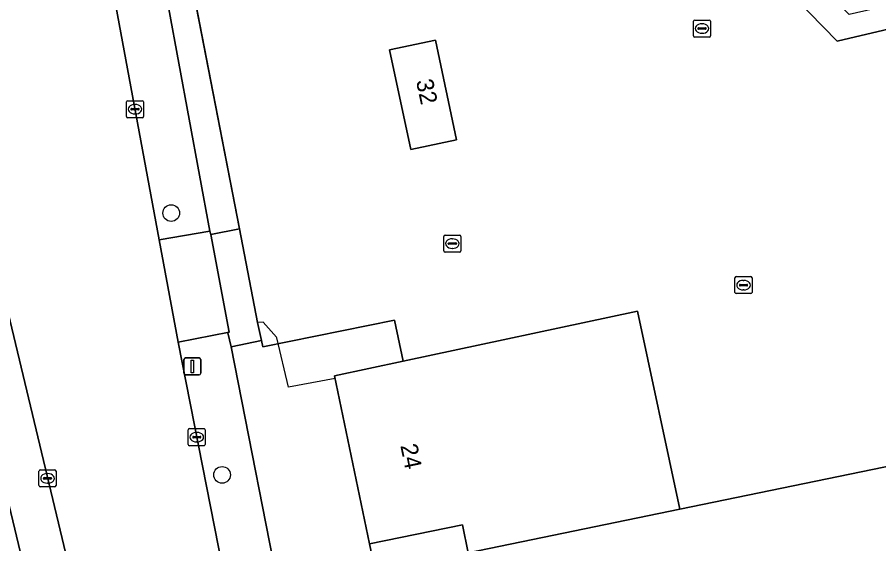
# Model space of a CAD drawing. Extents: x 162989 to 165008, y 383432 to 384338.
# Drawn here: x 164275.7 to 164326.4, y 384168.5 to 384199.5 of the extents above; entities that cross this region are included whole.
import ezdxf

# ---------------------------------------------------------------- set-up
doc = ezdxf.new("R2010")
doc.units = 0
for name, color, linetype in [('IMGEO_Boom', 7, 'Continuous'), ('IMGEO_Erf', 7, 'Continuous'), ('IMGEO_Groenvoorziening', 7, 'Continuous'), ('IMGEO_Hek', 7, 'Continuous'), ('IMGEO_Kolk', 7, 'Continuous'), ('IMGEO_Lichtmast', 7, 'Continuous'), ('IMGEO_Pand', 7, 'Continuous'), ('IMGEO_Pand_nummerreeks', 7, 'Continuous'), ('IMGEO_Rijbaan_lokaal_open', 7, 'Continuous'), ('IMGEO_Rioolput', 7, 'Continuous'), ('IMGEO_Voetpad_halfverhard', 7, 'Continuous'), ('IMGEO_Voetpad_open', 7, 'Continuous')]:
    doc.layers.add(name, color=color, linetype=linetype)

msp = doc.modelspace()

# ---------------------------------------------------------------- linework, layer by layer
at = {"layer": 'IMGEO_Boom'}
for centre in [(164284.791, 384187.967), (164287.78, 384172.593)]:
    msp.add_circle(centre, 0.489, dxfattribs=at)
at = {"layer": 'IMGEO_Erf'}
for points in [[(164352.012, 384189.272), (164351.666, 384190.951), (164349.03, 384203.686), (164345.88, 384203.022), (164345.767, 384203.225), (164323.902, 384198.058), (164310.007, 384212.304), (164284.923, 384207.017), (164288.795, 384187.032), (164289.861, 384181.531), (164290.088, 384180.487), (164290.168, 384180.119), (164297.901, 384181.683), (164298.416, 384179.266), (164312.176, 384182.207), (164314.663, 384170.574), (164349.272, 384177.712), (164354.784, 384150.783), (164357.983, 384135.415), (164362.896, 384136.438), (164362.509, 384138.318)], [(164301.552, 384192.268), (164298.858, 384191.689), (164297.623, 384197.555), (164300.321, 384198.122)]]:
    msp.add_lwpolyline(points, close=True, dxfattribs=at)
at = {"layer": 'IMGEO_Groenvoorziening'}
msp.add_lwpolyline([(164310.007, 384212.304), (164323.902, 384198.058), (164345.767, 384203.225), (164345.88, 384203.022), (164349.03, 384203.686), (164348.736, 384205.107), (164324.619, 384199.625), (164311.134, 384213.146)], close=True, dxfattribs=at)
msp.add_lwpolyline([(164279.829, 384151.74), (164269.173, 384196.228)], dxfattribs=at)
at = {"layer": 'IMGEO_Hek'}
for points in [[(164288.795, 384187.032), (164284.873, 384207.276)], [(164290.967, 384180.671), (164290.186, 384181.569), (164289.861, 384181.531), (164288.795, 384187.032)], [(164294.423, 384178.244), (164291.682, 384177.752), (164290.991, 384180.644), (164290.967, 384180.671)]]:
    msp.add_lwpolyline(points, dxfattribs=at)
at = {"layer": 'IMGEO_Kolk'}
for p, q in [((164282.24, 384194.562), (164283.092, 384194.562)), ((164282.165, 384193.636), (164282.165, 384194.488)), ((164282.424, 384194.056), (164282.424, 384194.068)), ((164282.862, 384194.019), (164282.464, 384194.019)), ((164282.467, 384194.105), (164282.865, 384194.105)), ((164282.653, 384194.342), (164282.678, 384194.342)), ((164282.908, 384194.068), (164282.908, 384194.056)), ((164283.166, 384194.488), (164283.166, 384193.636)), ((164283.092, 384193.562), (164282.24, 384193.562)), ((164282.676, 384193.782), (164282.651, 384193.782)), ((164300.805, 384185.746), (164300.805, 384186.598)), ((164300.88, 384186.672), (164301.732, 384186.672)), ((164301.293, 384186.452), (164301.318, 384186.452)), ((164301.806, 384186.598), (164301.806, 384185.746)), ((164301.064, 384186.166), (164301.064, 384186.178)), ((164301.502, 384186.129), (164301.104, 384186.129)), ((164301.107, 384186.215), (164301.505, 384186.215)), ((164301.548, 384186.178), (164301.548, 384186.166)), ((164301.732, 384185.672), (164300.88, 384185.672)), ((164301.316, 384185.892), (164301.291, 384185.892)), ((164317.906, 384183.308), (164317.906, 384184.16)), ((164317.981, 384184.234), (164318.833, 384184.234)), ((164318.394, 384184.014), (164318.419, 384184.014)), ((164318.907, 384184.16), (164318.907, 384183.308)), ((164318.165, 384183.728), (164318.165, 384183.74)), ((164318.603, 384183.691), (164318.205, 384183.691)), ((164318.208, 384183.777), (164318.606, 384183.777)), ((164318.417, 384183.454), (164318.392, 384183.454)), ((164318.649, 384183.74), (164318.649, 384183.728)), ((164318.833, 384183.234), (164317.981, 384183.234)), ((164285.869, 384175.308), (164286.721, 384175.308)), ((164285.794, 384174.382), (164285.794, 384175.234)), ((164286.053, 384174.802), (164286.053, 384174.814)), ((164286.096, 384174.851), (164286.494, 384174.851)), ((164286.282, 384175.088), (164286.307, 384175.088)), ((164286.537, 384174.814), (164286.537, 384174.802)), ((164286.795, 384175.234), (164286.795, 384174.382)), ((164286.721, 384174.308), (164285.869, 384174.308)), ((164286.491, 384174.765), (164286.093, 384174.765)), ((164286.305, 384174.528), (164286.28, 384174.528)), ((164277.026, 384171.961), (164277.026, 384172.813)), ((164277.101, 384172.887), (164277.953, 384172.887)), ((164278.027, 384172.813), (164278.027, 384171.961)), ((164277.285, 384172.381), (164277.285, 384172.393)), ((164277.723, 384172.344), (164277.325, 384172.344)), ((164277.328, 384172.43), (164277.726, 384172.43)), ((164277.514, 384172.667), (164277.539, 384172.667)), ((164277.769, 384172.393), (164277.769, 384172.381)), ((164277.953, 384171.887), (164277.101, 384171.887)), ((164277.537, 384172.107), (164277.512, 384172.107))]:
    msp.add_line(p, q, dxfattribs=at)
for points in [[(164282.24, 384194.562), (164283.092, 384194.562)], [(164282.165, 384193.636), (164282.165, 384194.488)], [(164283.166, 384194.488), (164283.166, 384193.636)], [(164283.092, 384193.562), (164282.24, 384193.562)], [(164300.805, 384185.746), (164300.805, 384186.598)], [(164300.88, 384186.672), (164301.732, 384186.672)], [(164301.806, 384186.598), (164301.806, 384185.746)], [(164301.732, 384185.672), (164300.88, 384185.672)], [(164317.906, 384183.308), (164317.906, 384184.16)], [(164317.981, 384184.234), (164318.833, 384184.234)], [(164318.907, 384184.16), (164318.907, 384183.308)], [(164318.833, 384183.234), (164317.981, 384183.234)], [(164285.869, 384175.308), (164286.721, 384175.308)], [(164285.794, 384174.382), (164285.794, 384175.234)], [(164286.795, 384175.234), (164286.795, 384174.382)], [(164286.721, 384174.308), (164285.869, 384174.308)], [(164277.026, 384171.961), (164277.026, 384172.813)], [(164277.101, 384172.887), (164277.953, 384172.887)], [(164278.027, 384172.813), (164278.027, 384171.961)], [(164277.953, 384171.887), (164277.101, 384171.887)]]:
    msp.add_lwpolyline(points, dxfattribs=at)
for centre, radius, start, end in [((164282.242, 384194.486), 0.0765, 91.552, 178.448), ((164282.242, 384194.486), 0.0765, 91.552, 178.448), ((164283.09, 384194.486), 0.0765, 1.552, 88.448), ((164283.09, 384194.486), 0.0765, 1.552, 88.448), ((164282.464, 384194.065), 0.0403, 85.8775, 175.7526), ((164282.461, 384194.055), 0.0366, 178.938, 274.7102), ((164282.865, 384194.062), 0.043, 264.8664, 352.4533), ((164282.869, 384194.067), 0.0386, 1.7309, 96.639), ((164282.242, 384193.638), 0.0765, 181.552, 268.448), ((164282.242, 384193.638), 0.0765, 181.552, 268.448), ((164283.09, 384193.638), 0.0765, 271.552, 358.448), ((164283.09, 384193.638), 0.0765, 271.552, 358.448), ((164300.882, 384186.596), 0.0765, 91.552, 178.448), ((164300.882, 384186.596), 0.0765, 91.552, 178.448), ((164301.73, 384186.596), 0.0765, 1.552, 88.448), ((164301.73, 384186.596), 0.0765, 1.552, 88.448), ((164301.104, 384186.175), 0.0403, 85.8775, 175.7526), ((164301.101, 384186.165), 0.0366, 178.938, 274.7102), ((164301.505, 384186.172), 0.043, 264.8664, 352.4533), ((164301.509, 384186.177), 0.0386, 1.7309, 96.639), ((164300.882, 384185.748), 0.0765, 181.552, 268.448), ((164300.882, 384185.748), 0.0765, 181.552, 268.448), ((164301.73, 384185.748), 0.0765, 271.552, 358.448), ((164301.73, 384185.748), 0.0765, 271.552, 358.448), ((164317.983, 384184.158), 0.0765, 91.552, 178.448), ((164317.983, 384184.158), 0.0765, 91.552, 178.448), ((164318.831, 384184.158), 0.0765, 1.552, 88.448), ((164318.831, 384184.158), 0.0765, 1.552, 88.448), ((164318.205, 384183.737), 0.0403, 85.8775, 175.7526), ((164318.202, 384183.727), 0.0366, 178.938, 274.7102), ((164318.606, 384183.734), 0.043, 264.8664, 352.4533), ((164318.61, 384183.739), 0.0386, 1.7309, 96.639), ((164317.983, 384183.31), 0.0765, 181.552, 268.448), ((164317.983, 384183.31), 0.0765, 181.552, 268.448), ((164318.831, 384183.31), 0.0765, 271.552, 358.448), ((164318.831, 384183.31), 0.0765, 271.552, 358.448), ((164285.871, 384175.232), 0.0765, 91.552, 178.448), ((164285.871, 384175.232), 0.0765, 91.552, 178.448), ((164286.719, 384175.232), 0.0765, 1.552, 88.448), ((164286.719, 384175.232), 0.0765, 1.552, 88.448), ((164286.093, 384174.811), 0.0403, 85.8775, 175.7526), ((164286.09, 384174.801), 0.0366, 178.938, 274.7102), ((164286.494, 384174.808), 0.043, 264.8664, 352.4533), ((164286.498, 384174.813), 0.0386, 1.7309, 96.639), ((164285.871, 384174.384), 0.0765, 181.552, 268.448), ((164285.871, 384174.384), 0.0765, 181.552, 268.448), ((164286.719, 384174.384), 0.0765, 271.552, 358.448), ((164286.719, 384174.384), 0.0765, 271.552, 358.448), ((164277.103, 384172.811), 0.0765, 91.552, 178.448), ((164277.103, 384172.811), 0.0765, 91.552, 178.448), ((164277.951, 384172.811), 0.0765, 1.552, 88.448), ((164277.951, 384172.811), 0.0765, 1.552, 88.448), ((164277.325, 384172.39), 0.0403, 85.8775, 175.7526), ((164277.322, 384172.38), 0.0366, 178.938, 274.7102), ((164277.726, 384172.387), 0.043, 264.8664, 352.4533), ((164277.73, 384172.392), 0.0386, 1.7309, 96.639), ((164277.103, 384171.963), 0.0765, 181.552, 268.448), ((164277.103, 384171.963), 0.0765, 181.552, 268.448), ((164277.951, 384171.963), 0.0765, 271.552, 358.448), ((164277.951, 384171.963), 0.0765, 271.552, 358.448)]:
    msp.add_arc(centre, radius, start, end, dxfattribs=at)
for centre, major_axis, ratio, start_param, end_param in [((164282.652, 384194.062), (-0.387, 0.002), 0.722429, 4.712389, 7.853982), ((164282.677, 384194.062), (-0.39, 0.002), 0.717154, 1.570796, 4.712389), ((164301.292, 384186.172), (-0.387, 0.002), 0.722429, 4.712389, 7.853982), ((164301.317, 384186.172), (-0.39, 0.002), 0.717154, 1.570796, 4.712389), ((164318.393, 384183.734), (-0.387, 0.002), 0.722429, 4.712389, 7.853982), ((164318.418, 384183.734), (-0.39, 0.002), 0.717154, 1.570796, 4.712389), ((164286.281, 384174.808), (-0.387, 0.002), 0.722429, 4.712389, 7.853982), ((164286.306, 384174.808), (-0.39, 0.002), 0.717154, 1.570796, 4.712389), ((164277.513, 384172.387), (-0.387, 0.002), 0.722429, 4.712389, 7.853982), ((164277.538, 384172.387), (-0.39, 0.002), 0.717154, 1.570796, 4.712389)]:
    msp.add_ellipse(centre, major_axis=major_axis, ratio=ratio, start_param=start_param, end_param=end_param, dxfattribs=at)
at = {"layer": 'IMGEO_Lichtmast'}
for p, q in [((164285.537, 384178.562), (164285.537, 384179.362)), ((164285.537, 384179.362), (164285.537, 384178.562)), ((164285.637, 384179.462), (164286.427, 384179.462)), ((164286.427, 384179.462), (164285.637, 384179.462)), ((164286.527, 384179.362), (164286.527, 384178.562)), ((164286.527, 384178.562), (164286.527, 384179.362)), ((164286.427, 384178.462), (164285.637, 384178.462)), ((164285.637, 384178.462), (164286.427, 384178.462))]:
    msp.add_line(p, q, dxfattribs=at)
msp.add_lwpolyline([(164285.957, 384179.337), (164286.107, 384179.337), (164286.107, 384178.587), (164285.957, 384178.587), (164285.957, 384179.337)], dxfattribs=at)
for centre, start, end in [((164285.637, 384179.362), 90, 180), ((164285.637, 384179.362), 90, 180), ((164286.427, 384179.362), 0, 90), ((164286.427, 384179.362), 360, 90), ((164285.637, 384178.562), 180, 270), ((164285.637, 384178.562), 180, 270), ((164286.427, 384178.562), 270, 0), ((164286.427, 384178.562), 270, 0)]:
    msp.add_arc(centre, 0.1, start, end, dxfattribs=at)
at = {"layer": 'IMGEO_Pand'}
for points in [[(164298.858, 384191.689), (164301.552, 384192.268), (164300.321, 384198.122), (164297.623, 384197.555)], [(164312.176, 384182.207), (164298.416, 384179.266), (164294.384, 384178.408), (164296.446, 384168.542), (164301.893, 384169.665), (164302.234, 384168.01), (164314.663, 384170.574)], [(164354.784, 384150.783), (164349.272, 384177.712), (164314.663, 384170.574), (164302.234, 384168.01), (164301.893, 384169.665), (164296.446, 384168.542), (164305.282, 384126.16), (164311.315, 384127.446), (164311.652, 384125.77), (164339.521, 384131.57), (164357.983, 384135.415)]]:
    msp.add_lwpolyline(points, close=True, dxfattribs=at)
at = {"layer": 'IMGEO_Rijbaan_lokaal_open'}
for points in [[(164285.193, 384180.381), (164284.089, 384186.389), (164278.538, 384216.318), (164277.123, 384223.939), (164264.967, 384221.376), (164271.917, 384195.775), (164282.629, 384151.118)], [(164282.769, 384148.733), (164287.477, 384131.405), (164289.232, 384131.808), (164290.539, 384126.149), (164294.921, 384127.125), (164293.661, 384132.762), (164295.367, 384133.159), (164293.981, 384139.327), (164292.295, 384146.556), (164291.539, 384149.798), (164290.373, 384154.797), (164289.565, 384158.641), (164289.321, 384159.803), (164288.3, 384164.665), (164285.193, 384180.381)]]:
    msp.add_lwpolyline(points, dxfattribs=at)
at = {"layer": 'IMGEO_Rioolput'}
for p, q in [((164315.469, 384198.372), (164315.469, 384199.224)), ((164315.544, 384199.298), (164316.396, 384199.298)), ((164315.957, 384199.078), (164315.982, 384199.078)), ((164316.47, 384199.224), (164316.47, 384198.372)), ((164315.728, 384198.792), (164315.728, 384198.804)), ((164316.166, 384198.755), (164315.768, 384198.755)), ((164315.771, 384198.841), (164316.169, 384198.841)), ((164316.212, 384198.804), (164316.212, 384198.792)), ((164316.396, 384198.298), (164315.544, 384198.298)), ((164315.98, 384198.518), (164315.955, 384198.518))]:
    msp.add_line(p, q, dxfattribs=at)
for points in [[(164315.469, 384198.372), (164315.469, 384199.224)], [(164315.544, 384199.298), (164316.396, 384199.298)], [(164316.47, 384199.224), (164316.47, 384198.372)], [(164316.396, 384198.298), (164315.544, 384198.298)]]:
    msp.add_lwpolyline(points, dxfattribs=at)
for centre, radius, start, end in [((164315.546, 384199.222), 0.0765, 91.552, 178.448), ((164315.546, 384199.222), 0.0765, 91.552, 178.448), ((164316.394, 384199.222), 0.0765, 1.552, 88.448), ((164316.394, 384199.222), 0.0765, 1.552, 88.448), ((164315.768, 384198.801), 0.0403, 85.8775, 175.7526), ((164315.765, 384198.791), 0.0366, 178.938, 274.7102), ((164316.169, 384198.798), 0.043, 264.8664, 352.4533), ((164316.173, 384198.803), 0.0386, 1.7309, 96.639), ((164315.546, 384198.374), 0.0765, 181.552, 268.448), ((164315.546, 384198.374), 0.0765, 181.552, 268.448), ((164316.394, 384198.374), 0.0765, 271.552, 358.448), ((164316.394, 384198.374), 0.0765, 271.552, 358.448)]:
    msp.add_arc(centre, radius, start, end, dxfattribs=at)
for centre, major_axis, ratio, start_param, end_param in [((164315.956, 384198.798), (-0.387, 0.002), 0.722429, 4.712389, 7.853982), ((164315.981, 384198.798), (-0.39, 0.002), 0.717154, 1.570796, 4.712389)]:
    msp.add_ellipse(centre, major_axis=major_axis, ratio=ratio, start_param=start_param, end_param=end_param, dxfattribs=at)
at = {"layer": 'IMGEO_Voetpad_halfverhard'}
for points in [[(164284.923, 384207.017), (164283.401, 384206.709), (164283.411, 384206.656), (164287.067, 384186.9), (164287.119, 384186.708), (164288.795, 384187.032)], [(164296.446, 384168.542), (164294.384, 384178.408), (164298.416, 384179.266), (164297.901, 384181.683), (164290.168, 384180.119), (164290.088, 384180.487), (164288.313, 384180.115), (164291.397, 384164.464), (164293.215, 384156.373), (164296.763, 384140.464), (164300.887, 384123.541), (164301.901, 384123.755), (164305.62, 384124.539), (164305.282, 384126.16)]]:
    msp.add_lwpolyline(points, close=True, dxfattribs=at)
at = {"layer": 'IMGEO_Voetpad_open'}
for points in [[(164283.411, 384206.656), (164283.401, 384206.709), (164282.785, 384210.037), (164282.496, 384211.599), (164281.369, 384217.691), (164282.371, 384220.633), (164282.125, 384221.916), (164282.071, 384222.197), (164281.475, 384222.094), (164280.909, 384224.737), (164280.836, 384224.722), (164279.3, 384224.398), (164280.036, 384220.835), (164278.538, 384216.318), (164284.089, 384186.389), (164287.067, 384186.9)], [(164288.795, 384187.032), (164287.119, 384186.708), (164288.201, 384180.968), (164288.119, 384180.939), (164288.313, 384180.115), (164290.088, 384180.487), (164289.861, 384181.531)], [(164288.201, 384180.968), (164287.119, 384186.708), (164287.067, 384186.9), (164284.089, 384186.389), (164285.193, 384180.381)]]:
    msp.add_lwpolyline(points, close=True, dxfattribs=at)
for points in [[(164264.967, 384221.376), (164262.446, 384220.844), (164262.653, 384220.092), (164262.732, 384219.802), (164263.401, 384217.372), (164265.013, 384211.511), (164265.331, 384210.398), (164269.173, 384196.228), (164279.829, 384151.74), (164281.927, 384146.498)], [(164282.629, 384151.118), (164271.917, 384195.775), (164264.967, 384221.376)], [(164293.215, 384156.373), (164291.397, 384164.464), (164288.313, 384180.115), (164288.119, 384180.939), (164288.201, 384180.968), (164285.193, 384180.381), (164288.3, 384164.665), (164289.48, 384164.912), (164290.482, 384160.079), (164289.321, 384159.803), (164289.565, 384158.641), (164290.708, 384158.884), (164291.567, 384155.071), (164290.373, 384154.797), (164291.539, 384149.798), (164293.737, 384150.308), (164294.495, 384147.079), (164292.295, 384146.556), (164293.981, 384139.327), (164295.367, 384133.159), (164296.535, 384127.939), (164296.654, 384127.492), (164297.422, 384123.939)]]:
    msp.add_lwpolyline(points, dxfattribs=at)

# ---------------------------------------------------------------- texts
at = {"layer": 'IMGEO_Pand_nummerreeks'}
for s, rotation, p in [('32', 282.0261, (164299.165, 384195.723)), ('24', 281.86, (164298.244, 384174.314))]:
    msp.add_text(s, height=1, rotation=rotation, dxfattribs=at).set_placement(p)

doc.saveas('drawing.dxf')
